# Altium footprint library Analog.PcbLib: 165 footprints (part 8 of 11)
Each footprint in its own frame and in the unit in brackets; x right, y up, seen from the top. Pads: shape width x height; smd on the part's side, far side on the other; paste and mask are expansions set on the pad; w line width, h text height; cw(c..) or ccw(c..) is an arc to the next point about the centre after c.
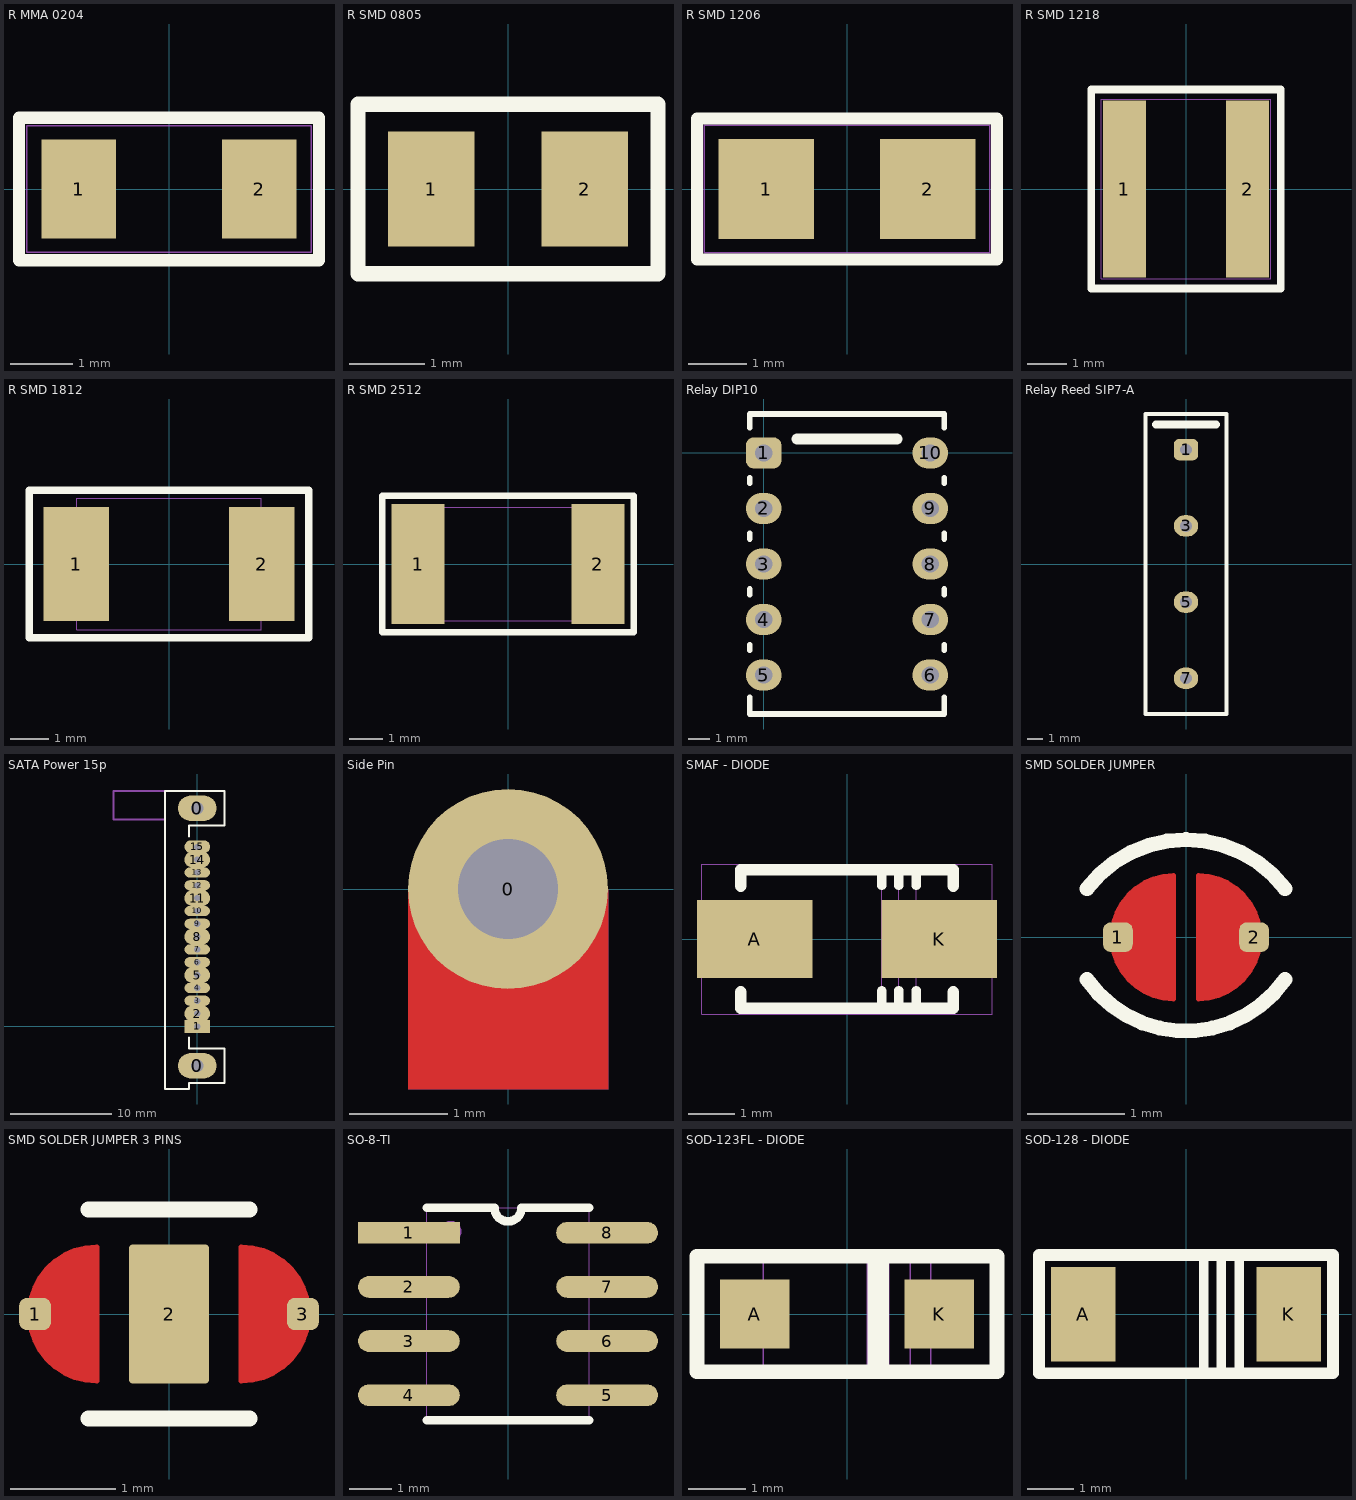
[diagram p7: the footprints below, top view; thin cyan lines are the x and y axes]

## R MMA 0204 [mm]
height 1.473
pads (2):
  rect 1.2x1.6 smd: 1(-1.45,0) 2(1.45,0)
Top Overlay:
  lines w0.2: -2.413,-1.143 2.413,-1.143 2.413,1.143 -2.413,1.143 -2.413,-1.143
Mechanical 13:
  lines w0.025: -2.286,-1.016 -2.286,1.016 2.286,1.016 2.286,-1.016 -2.286,-1.016
  text ".Designator" at -1.93,-0.457 h1.02

## R SMD 0805 [mil]
pads (2):
  rect 45x60 smd: 1(-40,0) 2(40,0)
Top Overlay:
  lines w8: -78,-44 78,-44 78,44 -78,44 -78,-44
Mechanical 13:
  lines w1: -78,-44 -78,44 78,44 78,-44 -78,-44
  text ".Designator" at -70,-19 h40

## R SMD 1206 [mil]
pads (2):
  rect 65x68 smd: 1(-55,0) 2(55,0)
Top Overlay:
  lines w8: -102,-48 102,-48 102,48 -102,48 -102,-48
Mechanical 13:
  lines w1: -97,-43.31 -97,43.31 97,43.31 97,-43.31 -97,-43.31
  text ".Designator" at -89,-21 h40

## R SMD 1218 [mm]
pads (2):
  rect 1.1x4.5 smd: 1(-1.57,0) 2(1.57,0)
Top Overlay:
  lines w0.203: -2.413,-2.54 2.413,-2.54 2.413,2.54 -2.413,2.54 -2.413,-2.54
Mechanical 13:
  lines w0.025: -2.159,-2.286 2.159,-2.286 2.159,2.286 -2.159,2.286 -2.159,-2.286
  text ".Designator" at 0.381,-2.032 h1.02

## R SMD 1812 [mm]
height 0.85
pads (2):
  rect 1.68x2.95 smd: 1(-2.39,0) 2(2.39,0)
Top Overlay:
  lines w0.203: -3.6,-1.9 3.6,-1.9 3.6,1.9 -3.6,1.9 -3.6,-1.9
Mechanical 13:
  lines w0.025: -2.375,-1.7 2.375,-1.7 2.375,1.7 -2.375,1.7 -2.375,-1.7
  text ".Designator" at 0.4,-1.5 h1.02

## R SMD 2512 [mm]
height 0.85
pads (2):
  rect 1.6x3.6 smd: 1(-2.7,0) 2(2.7,0)
Top Overlay:
  lines w0.203: -3.775,-2.05 -3.775,2.05 3.775,2.05 3.775,-2.05 -3.775,-2.05
Mechanical 13:
  lines w0.025: -3.15,-1.7 -3.15,1.7 3.15,1.7 3.15,-1.7 -3.15,-1.7
  text ".Designator" at 0.4,-1.5 h1.02

## Relay DIP10 [mil]
height 200
pads (10):
  rrect50% 64x56 hole 31: 1(0,0)
  oval 64x56 hole 31: 2(0,-100) 3(0,-200) 4(0,-300) 5(0,-400) 6(300,-400) 7(300,-300) 8(300,-200) 9(300,-100) 10(300,0)
Top Overlay:
  lines w10: -25,-440 -25,-470 325,-470 325,-440 ; -25,-355 -25,-345 ; -25,-255 -25,-245 ; -25,-155 -25,-145 ; -25,-55 -25,-45 ; -25,45 -25,70 325,70 325,45 ; 325,-355 325,-345 ; 325,-255 325,-245 ; 325,-155 325,-145 ; 325,-55 325,-45
  lines w20: 60,25 240,25

## Relay Reed SIP7-A [mil]
height 200
pads (4):
  rrect50% 64x56 hole 31: 1(0,300)
  oval 64x56 hole 31: 3(0,100) 5(0,-100) 7(0,-300)
Top Overlay:
  lines w10: -106.3,-393.7 -106.3,393.7 106.3,393.7 106.3,-393.7 -106.3,-393.7
  lines w20: -78.74,366.14 78.74,366.14

## SATA Power 15p [mm]
pads (17):
  oval 3.81x2.54 hole 1.27: 0(0,-3.9) 0(0,21.6)
  rect 2.54x1.3 hole 0.6: 1(0,0)
  oval 2.54x1.6 hole 0.6: 2(0,1.27) 5(0,5.08) 8(0,8.89) 11(0,12.7) 14(0,16.51)
  oval 2.54x1 hole 0.6: 3(0,2.54) 4(0,3.81) 6(0,6.35) 7(0,7.62) 9(0,10.16) 10(0,11.43) 12(0,13.97) 13(0,15.24)
  oval 2.54x1.3 hole 0.6: 15(0,17.78)
Top Overlay:
  lines w0.2: -0.8,-1.1 -0.8,-2.2 2.7,-2.2 2.7,-5.6 -0.8,-5.6 -0.8,-6.2 -3.2,-6.2 -3.2,23.3 2.7,23.3 2.7,19.9 -0.8,19.9 -0.8,18.8
Mechanical 13:
  lines w0.2: -3.2,20.5 -8.3,20.5 -8.3,23.3 -3.2,23.3

## Side Pin [mil]
pads (1):
  round 80 hole 40: 0(0,0)
Top Layer:
  region: -40,0 -40,-80 40,-80 40,0
Bottom Layer:
  region: -40,0 -40,-80 40,-80 40,0

## SMAF - DIODE [mm]
pads (2):
  rect 2.5x1.7 smd: A(-2,0) K(2,0)
Top Overlay:
  lines w0.203: 0.75,-1.465 0.75,-1.125 ; 0.75,1.16 0.75,1.5 ; 1.125,-1.465 1.125,-1.115 ; 1.125,1.16 1.125,1.51 ; 1.5,-1.465 1.5,-1.115 ; 1.5,1.16 1.5,1.51
  lines w0.254: -2.3,-1.15 -2.3,-1.5 2.3,-1.5 2.3,-1.15 ; -2.3,1.15 -2.3,1.5 2.3,1.5 2.3,1.15
Mechanical 13:
  lines w0.025: 0.75,-1.625 0.75,1.625 ; 1.125,-1.625 1.125,1.625 ; 1.5,-1.625 1.5,1.625 ; -3.15,-1.625 -3.15,1.625 3.15,1.625 3.15,-1.625 -3.15,-1.625
  text ".Designator" at -2.794,-0.483 h1.02

## SMD SOLDER JUMPER [mil]
pads (2):
  rrect50% 12x12 smd paste-6: 1(-27.56,0) 2(27.56,0)
Top Layer:
  region: -5,-25 -9.97,-25 -19.16,-21.19 -26.19,-14.16 -30,-4.97 -30,4.97 -26.19,14.16 -19.16,21.19 -9.97,25 -5,25
  region: 5,-25 5,25 9.97,25 19.16,21.19 26.19,14.16 30,4.97 30,-4.97 26.19,-14.16 19.16,-21.19 9.97,-25
  lines w2: -5,-25 cw(c-5,0) -5,25 -5,-25 ; 5,-25 ccw(c5,0) 5,25 5,-25
Top Overlay:
  lines w6: -40.17,-17.12 ccw(c0,11) 40.17,-17.12 ; -40.17,19.63 cw(c0,-11) 40.17,19.63
Top Solder:
  lines w6: 0,-20 0,20

## SMD SOLDER JUMPER 3 PINS [mil]
pads (3):
  rrect50% 12x12 smd paste-6: 1(-50,0) 3(50,0)
  rrect10% 30x52 smd paste-52: 2(0,0)
Top Layer:
  region: -27,-25 -31.97,-25 -41.16,-21.19 -48.19,-14.16 -52,-4.97 -52,4.97 -48.19,14.16 -41.16,21.19 -31.97,25 -27,25
  region: 27,25 31.97,25 41.16,21.19 48.19,14.16 52,4.97 52,-4.97 48.19,-14.16 41.16,-21.19 31.97,-25 27,-25
  lines w2: -27,-25 cw(c-27,0) -27,25 -27,-25 ; 27,-25 ccw(c27,0) 27,25 27,-25
Top Overlay:
  lines w6: -30,-39 30,-39 ; -30,39 30,39
Top Solder:
  lines w6: -23,-20 -23,20 ; -19,-20 -19,20 ; 19,-20 19,20 ; 23,-20 23,20

## SO-8-TI [mil]
pads (8):
  rect 94x20 smd: 1(-91.5,75)
  oval 94x20 smd: 2(-91.5,25) 3(-91.5,-25) 4(-91.5,-75) 5(91.5,-75) 6(91.5,-25) 7(91.5,25) 8(91.5,75)
Top Overlay:
  lines w8: -75,-98 75,-98 ; -75,98 -12.5,98 ccw(c0,98) 12.5,98 75,98
Mechanical 13:
  circle w10: c-53,76 r5
  lines w1: -75,-98 -75,98 75,98 75,-98 -75,-98
  text ".Designator" at -10,75 h40

## SOD-123FL - DIODE [mm]
height 1.1
pads (2):
  rect 1.2x1.2 smd: A(-1.6,0) K(1.6,0)
Top Overlay:
  lines w0.203: 0.456,-1 0.456,1 ; 0.625,-1 0.625,1
  lines w0.254: -2.6,-1 -2.6,1 2.6,1 2.6,-1 -2.6,-1
Mechanical 13:
  lines w0.025: 0.35,-0.95 0.35,0.95 ; 0.725,-0.95 0.725,0.95 ; 1.1,-0.95 1.1,0.95 ; -1.45,-0.95 1.45,-0.95 1.45,0.95 -1.45,0.95 -1.45,-0.95
  text ".Designator" at -2.4,-0.4 h1.02

## SOD-128 - DIODE [mil]
pads (2):
  rect 55x80 smd: A(-87,0) K(87,0)
Top Overlay:
  lines w8: 15,-50 15,50 ; 30,-50 30,50 ; 45,-45 45,50
  lines w10: -124.5,-50 -124.5,0 -124.5,50 124.5,50 124.5,-50 -124.5,-50
Mechanical 13:
  lines w1: 15.75,-49.21 15.75,50.2 ; 30.51,-49.21 30.51,50.2 ; 45.28,-49.21 45.28,50.2 ; -124.02,-49.21 -124.02,50.2 124.02,50.2 124.02,-49.21 -124.02,-49.21
  text ".Designator" at -110,-19 h40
